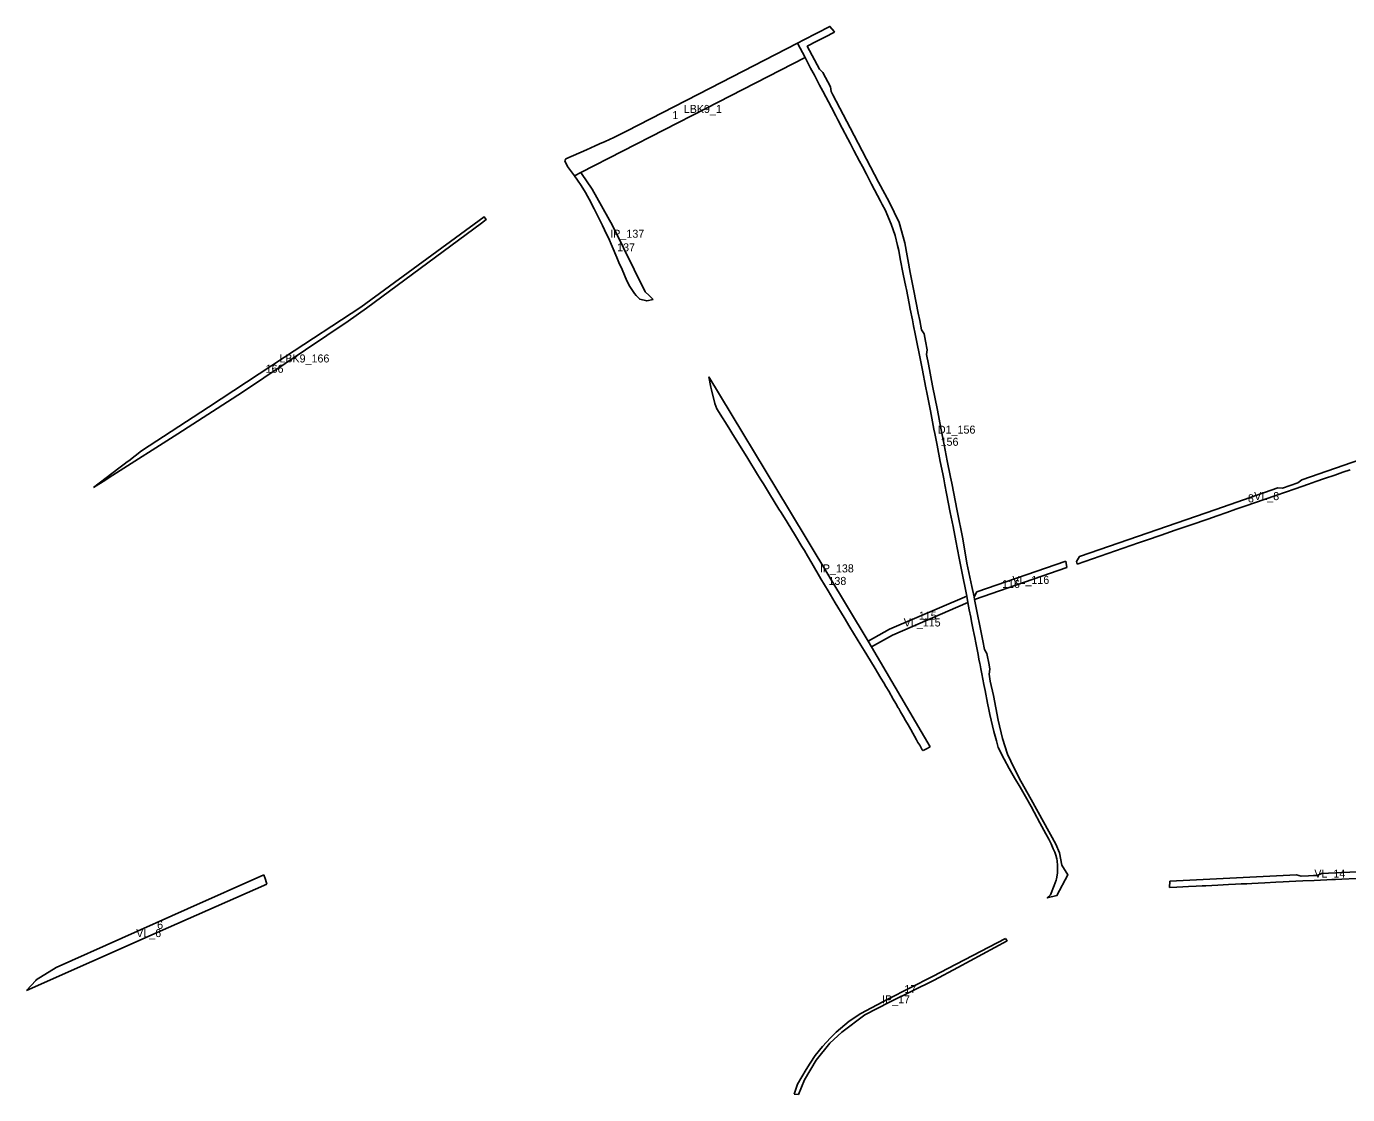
# Model space of a CAD drawing. Extents: x -521939 to -518034, y -1194984 to -1189555.
# Drawn here: x -521548 to -519897, y -1190889 to -1189555 of the extents above; entities that cross this region are included whole.
import ezdxf

# ---------------------------------------------------------------- set-up
doc = ezdxf.new("R2010")
doc.units = 0
for name, color, linetype in [('96120023', 7, 'Continuous'), ('96140023', 7, 'Continuous'), ('ID VPO', 7, 'Continuous'), ('ID VPS', 7, 'Continuous')]:
    doc.layers.add(name, color=color, linetype=linetype)

msp = doc.modelspace()

# ---------------------------------------------------------------- linework, layer by layer
at = {"layer": '96120023'}
for points in [[(-520538.07, -1189562.04), (-520538.7, -1189561.06), (-520543.9, -1189554.92), (-520576.33, -1189571.62), (-520584.33, -1189575.74), (-520574.91, -1189593.69), (-520571.87, -1189599.49), (-520567.98, -1189606.88), (-520563.29, -1189615.69), (-520556.78, -1189628.12), (-520554.77, -1189631.94), (-520552.78, -1189635.77), (-520542.06, -1189656.2), (-520536.5, -1189666.75), (-520533.97, -1189671.56), (-520528.55, -1189681.89), (-520521.58, -1189695.28), (-520518.55, -1189700.78), (-520513.98, -1189709.68), (-520506.96, -1189723.04), (-520503.29, -1189730.03), (-520498.25, -1189739.55), (-520491.89, -1189751.79), (-520480.47, -1189773.36), (-520478.5, -1189777.12), (-520474.96, -1189783.97), (-520467.22, -1189801.74), (-520462.52, -1189816.05), (-520459.4, -1189828.36), (-520457.93, -1189834.89), (-520455.88, -1189845.31), (-520452.13, -1189864.14), (-520448.96, -1189880.06), (-520448.32, -1189883.37), (-520444.85, -1189900.94), (-520443.47, -1189908.13), (-520440.81, -1189921.53), (-520439.37, -1189928.74), (-520437.33, -1189939.01), (-520429.98, -1189976.03), (-520428.73, -1189982.35), (-520424.06, -1190006.15), (-520422.85, -1190012.32), (-520421.24, -1190020.5), (-520418.36, -1190035.16), (-520413.93, -1190058), (-520412.81, -1190063.42), (-520409.99, -1190077.75), (-520405.98, -1190098.21), (-520402.94, -1190113.68), (-520401.68, -1190120.11), (-520400.22, -1190127.57), (-520398.08, -1190138.46), (-520393.44, -1190162.05), (-520389.99, -1190179.56), (-520386.49, -1190197.4), (-520382.22, -1190219.18), (-520379.42, -1190233.48), (-520372.97, -1190266.32)], [(-520371.58, -1190274.42), (-520369.76, -1190283.42), (-520368, -1190292.59), (-520366.87, -1190298.24), (-520364.88, -1190308.35), (-520363.75, -1190314.16), (-520362.96, -1190318.16), (-520361.67, -1190324.78), (-520358.8, -1190339.19), (-520357.64, -1190345.16), (-520356.65, -1190350.44), (-520356.28, -1190352.2), (-520355.24, -1190357.44), (-520354.1, -1190363.35), (-520352.77, -1190370.15), (-520351.48, -1190376.69), (-520349.98, -1190384.24), (-520346.85, -1190400.25), (-520345.34, -1190407.94), (-520344.11, -1190414.17), (-520339.16, -1190435.68), (-520335.69, -1190447.27), (-520333.6, -1190455.52), (-520326.28, -1190470.19), (-520319.79, -1190481.7), (-520313.06, -1190493.24), (-520306.18, -1190505.19), (-520299.49, -1190516.65), (-520292.56, -1190529.3), (-520288.83, -1190536.11), (-520281.56, -1190549.39), (-520273.96, -1190563.31), (-520270.32, -1190570.06), (-520267.58, -1190575.89), (-520264.82, -1190581.96), (-520262.79, -1190586.33), (-520261.69, -1190589.95), (-520260.46, -1190594.42), (-520260.08, -1190597.14), (-520259.34, -1190602.74), (-520259.34, -1190604.41), (-520259.47, -1190611.1), (-520259.64, -1190612.41), (-520260.77, -1190619.4), (-520261.32, -1190621), (-520263.6, -1190628.04), (-520268.22, -1190639.47), (-520272.31, -1190643.28), (-520260.36, -1190640.4), (-520246.6, -1190614.37), (-520254.03, -1190602.44), (-520256.94, -1190586.97), (-520261.73, -1190576.17), (-520292.37, -1190520.37), (-520305.38, -1190497.4), (-520313.7, -1190481.31), (-520322.01, -1190463.84), (-520328.19, -1190444.19), (-520333.62, -1190421.51), (-520339.48, -1190390.73), (-520343.5, -1190372.52), (-520344.85, -1190363.88), (-520343.97, -1190357.86), (-520345.06, -1190352.29), (-520347.86, -1190338.07), (-520350.9, -1190332.99), (-520352.86, -1190322.18), (-520363.12, -1190270.76), (-520363.78, -1190267.42), (-520366.37, -1190254.23), (-520372.66, -1190225.12), (-520377.99, -1190195.02), (-520384.87, -1190160.07), (-520391.56, -1190125.16), (-520393.2, -1190117.89), (-520397.27, -1190097.65), (-520401.22, -1190077.65), (-520405.21, -1190056.77), (-520409.61, -1190034.24), (-520415.58, -1190003.82), (-520420.88, -1189976.82), (-520423.3, -1189964.53), (-520422.41, -1189958.68), (-520424.49, -1189948.09), (-520426.3, -1189938.88), (-520429.34, -1189933.8), (-520431.66, -1189922.07), (-520433.46, -1189912.89), (-520438.94, -1189885.01), (-520443.42, -1189862.15), (-520450.25, -1189825.06), (-520457.28, -1189799.95), (-520463.47, -1189786.79), (-520469.68, -1189773.95), (-520483.13, -1189749.49), (-520518.67, -1189681.41), (-520540.29, -1189640.25), (-520542.46, -1189636.12), (-520543.28, -1189630.26), (-520552.66, -1189612.4), (-520557.02, -1189608.4), (-520572.14, -1189579.59), (-520568.14, -1189577.53), (-520564.14, -1189575.47), (-520555.14, -1189570.83), (-520546.14, -1189566.2), (-520542.1, -1189564.12), (-520538.07, -1189562.04)], [(-520855.05, -1189737.39), (-520862.97, -1189741.45)], [(-520854.52, -1189738.05), (-520855.05, -1189737.39)], [(-520769.62, -1189891.18), (-520774.69, -1189886.48), (-520815.47, -1189803.6), (-520840.73, -1189757.97), (-520853.99, -1189738.71), (-520854.52, -1189738.05)], [(-520862.97, -1189741.45), (-520859.09, -1189746.74)], [(-520859.09, -1189746.74), (-520854.49, -1189753.78)], [(-520854.49, -1189753.78), (-520848.98, -1189762.26)], [(-520848.98, -1189762.26), (-520842.22, -1189775.08)], [(-520842.22, -1189775.08), (-520840.25, -1189778.89)], [(-520840.25, -1189778.89), (-520838.28, -1189782.7)], [(-520838.28, -1189782.7), (-520827.89, -1189803.41)], [(-520827.89, -1189803.41), (-520822.82, -1189814.19)], [(-520822.82, -1189814.19), (-520820.55, -1189819.14)], [(-520820.55, -1189819.14), (-520815.85, -1189829.79)], [(-520815.85, -1189829.79), (-520809.87, -1189843.72)], [(-520809.87, -1189843.72), (-520807.32, -1189849.61)], [(-520807.32, -1189849.61), (-520803.4, -1189858.68)], [(-520803.4, -1189858.68), (-520797.65, -1189872.73)], [(-520797.65, -1189872.73), (-520793.8, -1189879.57)], [(-520793.8, -1189879.57), (-520788.07, -1189888.65)], [(-520788.07, -1189888.65), (-520785.91, -1189890.86)], [(-520785.91, -1189890.86), (-520781.3, -1189895.57), (-520772.63, -1189897.76), (-520764.56, -1189895.88)], [(-520764.56, -1189895.88), (-520769.62, -1189891.18)], [(-520595.57, -1190157.59), (-520694.98, -1189992.45)], [(-520694.98, -1189992.45), (-520692.55, -1190005.5)], [(-520692.55, -1190005.5), (-520691.84, -1190008.79)], [(-520691.84, -1190008.79), (-520687.51, -1190025.96)], [(-520687.51, -1190025.96), (-520685.06, -1190032.49)], [(-520685.06, -1190032.49), (-520678.04, -1190043.73)], [(-520678.04, -1190043.73), (-520674.3, -1190049.78)], [(-520674.3, -1190049.78), (-520668.96, -1190058.36)], [(-519742.92, -1190048.01), (-519787.45, -1190063.39), (-519954.51, -1190121.09), (-519959.21, -1190124.83), (-519978.27, -1190131.41), (-519984.27, -1190131.37), (-520061.95, -1190158.2), (-520231.96, -1190216.92), (-520235.61, -1190223.15)], [(-520668.96, -1190058.36), (-520664.99, -1190064.75), (-520649.81, -1190089.25)], [(-520649.81, -1190089.25), (-520646.54, -1190094.49)], [(-520646.54, -1190094.49), (-520634.26, -1190114.38)], [(-520634.26, -1190114.38), (-520630.08, -1190121.08)], [(-519936.96, -1190123.44), (-519926.15, -1190119.68)], [(-519926.15, -1190119.68), (-519913.25, -1190115.28)], [(-519913.25, -1190115.28), (-519903.02, -1190111.63)], [(-519903.02, -1190111.63), (-519893.94, -1190108.6)], [(-520630.08, -1190121.08), (-520626.81, -1190126.38)], [(-520626.81, -1190126.38), (-520619.25, -1190138.59)], [(-519986.68, -1190140.64), (-519962.62, -1190132.36)], [(-519962.62, -1190132.36), (-519946.2, -1190126.69)], [(-519946.2, -1190126.69), (-519936.96, -1190123.44)], [(-520619.25, -1190138.59), (-520607.45, -1190157.65)], [(-520024.36, -1190153.64), (-520013.6, -1190149.97)], [(-520013.6, -1190149.97), (-519986.68, -1190140.64)], [(-520607.45, -1190157.65), (-520604.7, -1190162.17)], [(-520604.7, -1190162.17), (-520597.31, -1190174.18)], [(-520496.15, -1190322.74), (-520595.57, -1190157.59)], [(-520071.81, -1190170.12), (-520060.18, -1190166.05), (-520048.21, -1190161.91)], [(-520048.21, -1190161.91), (-520036.77, -1190157.93)], [(-520036.77, -1190157.93), (-520024.36, -1190153.64)], [(-520597.31, -1190174.18), (-520586.78, -1190191.32)], [(-520129.95, -1190190.13), (-520112.49, -1190184.08)], [(-520112.49, -1190184.08), (-520092.49, -1190177.21)], [(-520092.49, -1190177.21), (-520071.81, -1190170.12)], [(-520586.78, -1190191.32), (-520578.85, -1190204.26)], [(-520235.01, -1190226.44), (-520158.52, -1190200.01)], [(-520158.52, -1190200.01), (-520148.48, -1190196.56)], [(-520148.48, -1190196.56), (-520129.95, -1190190.13)], [(-520578.85, -1190204.26), (-520575.54, -1190209.65)], [(-520575.54, -1190209.65), (-520571.92, -1190216.03)], [(-520571.92, -1190216.03), (-520566.46, -1190225.16)], [(-520566.46, -1190225.16), (-520555.01, -1190244.86)], [(-520249.16, -1190222.86), (-520360.13, -1190261.18), (-520363.78, -1190267.42)], [(-520363.12, -1190270.76), (-520247.81, -1190230.86)], [(-520247.81, -1190230.86), (-520249.16, -1190222.86)], [(-520235.61, -1190223.15), (-520235.01, -1190226.44)], [(-520555.01, -1190244.86), (-520546, -1190259.94)], [(-520546, -1190259.94), (-520537.12, -1190274.8)], [(-520372.97, -1190266.32), (-520469.39, -1190307.83)], [(-520371.58, -1190274.42), (-520372.97, -1190266.32)], [(-520372.97, -1190266.32), (-520371.58, -1190274.42)], [(-520363.78, -1190267.42), (-520363.12, -1190270.76)], [(-520537.12, -1190274.8), (-520525.87, -1190293.08)], [(-520465.85, -1190315.02), (-520371.58, -1190274.42)], [(-520525.87, -1190293.08), (-520518.77, -1190305.18)], [(-520518.77, -1190305.18), (-520505.06, -1190327.7)], [(-520469.39, -1190307.83), (-520496.15, -1190322.74)], [(-520492.06, -1190329.61), (-520465.85, -1190315.02)], [(-520505.06, -1190327.7), (-520500.89, -1190334.53)], [(-520500.89, -1190334.53), (-520493.14, -1190347.28)], [(-520492.06, -1190329.61), (-520496.15, -1190322.74)], [(-520496.15, -1190322.74), (-520492.06, -1190329.61)], [(-520418.63, -1190454.51), (-520492.06, -1190329.61)], [(-520493.14, -1190347.28), (-520487.23, -1190356.63)], [(-520487.23, -1190356.63), (-520484.26, -1190361.73)], [(-520484.26, -1190361.73), (-520480.03, -1190368.97)], [(-520480.03, -1190368.97), (-520476.65, -1190374.74)], [(-520476.65, -1190374.74), (-520474.06, -1190379.19)], [(-520474.06, -1190379.19), (-520470.42, -1190385.29)], [(-520470.42, -1190385.29), (-520464.79, -1190395.13)], [(-520464.79, -1190395.13), (-520461.6, -1190400.68)], [(-520461.6, -1190400.68), (-520458.54, -1190405.84)], [(-520458.54, -1190405.84), (-520457.88, -1190406.97)], [(-520457.88, -1190406.97), (-520455.54, -1190411.02)], [(-520455.54, -1190411.02), (-520452.05, -1190417.09)], [(-520452.05, -1190417.09), (-520449.33, -1190421.77)], [(-520449.33, -1190421.77), (-520446.15, -1190427.25)], [(-520446.15, -1190427.25), (-520442.94, -1190432.82)], [(-520442.94, -1190432.82), (-520435.78, -1190445.73)], [(-520435.78, -1190445.73), (-520433.93, -1190449.11), (-520431.58, -1190452.47)], [(-520431.58, -1190452.47), (-520428.66, -1190458.29), (-520427.37, -1190459.39)], [(-520427.37, -1190459.39), (-520423.37, -1190457.05)], [(-520423.37, -1190457.05), (-520418.63, -1190454.51)], [(-521251.04, -1190614.64), (-521346.43, -1190657.14), (-521510.56, -1190730.26)], [(-521249.05, -1190620.36), (-521251.04, -1190614.64)], [(-519955.34, -1190616.3), (-519961.08, -1190614.58), (-520119.28, -1190622.29)], [(-519939.78, -1190615.54), (-519946.03, -1190615.85)], [(-519693.24, -1190601.52), (-519752.34, -1190604.4), (-519929.64, -1190613.04), (-519935.19, -1190615.32), (-519939.78, -1190615.54)], [(-521384.14, -1190686.63), (-521247.06, -1190626.08)], [(-521247.06, -1190626.08), (-521249.05, -1190620.36)], [(-520119.28, -1190622.29), (-520119.46, -1190630.32)], [(-520119.46, -1190630.32), (-520110.38, -1190629.91)], [(-520110.38, -1190629.91), (-520102.91, -1190629.55)], [(-520102.91, -1190629.55), (-520095.81, -1190629.12)], [(-520095.81, -1190629.12), (-520086.43, -1190628.7)], [(-520086.43, -1190628.7), (-520078.68, -1190628.32)], [(-520078.68, -1190628.32), (-520074.1, -1190628.1)], [(-520074.1, -1190628.1), (-520059.37, -1190627.38)], [(-520059.37, -1190627.38), (-520045.77, -1190626.72)], [(-520045.77, -1190626.72), (-520037.2, -1190626.26)], [(-520037.2, -1190626.26), (-520030.12, -1190625.96)], [(-520030.12, -1190625.96), (-520023.13, -1190625.6)], [(-520023.13, -1190625.6), (-520016.69, -1190625.32)], [(-520016.69, -1190625.32), (-520008.95, -1190624.91)], [(-520008.95, -1190624.91), (-520000.46, -1190624.51)], [(-520000.46, -1190624.51), (-519986.76, -1190623.81)], [(-519986.76, -1190623.81), (-519977.56, -1190623.39)], [(-519977.56, -1190623.39), (-519970.21, -1190623.03)], [(-519970.21, -1190623.03), (-519961.73, -1190622.55)], [(-519961.73, -1190622.55), (-519953.25, -1190622.2)], [(-519946.03, -1190615.85), (-519955.34, -1190616.3)], [(-519953.25, -1190622.2), (-519938.98, -1190621.52)], [(-519938.98, -1190621.52), (-519923.22, -1190620.76)], [(-519923.22, -1190620.76), (-519916.75, -1190620.41)], [(-519916.75, -1190620.41), (-519912.12, -1190620.15)], [(-519912.12, -1190620.15), (-519904.19, -1190619.79)], [(-519904.19, -1190619.79), (-519886.32, -1190618.93)], [(-521547.56, -1190758.81), (-521384.14, -1190686.63)], [(-520579.33, -1190879.67), (-520575.39, -1190870.36), (-520560.86, -1190845.88), (-520544.03, -1190824.72), (-520528.99, -1190810.95), (-520500.11, -1190789.41), (-520469.27, -1190773.73), (-520413.62, -1190746.07), (-520383.85, -1190730.39), (-520322.54, -1190696.8), (-520323.5, -1190695.35)], [(-520324.46, -1190693.89), (-520386.14, -1190726.13)], [(-520323.5, -1190695.35), (-520324.46, -1190693.89)], [(-521510.56, -1190730.26), (-521535.38, -1190745.68)], [(-520386.14, -1190726.13), (-520415.61, -1190741.57)], [(-521535.38, -1190745.68), (-521536.01, -1190746.36), (-521547.56, -1190758.81)], [(-520415.61, -1190741.57), (-520471.38, -1190769.62), (-520505.39, -1190787.53)], [(-520505.39, -1190787.53), (-520519.61, -1190797.43), (-520536.03, -1190811)], [(-520536.03, -1190811), (-520543.12, -1190818.16)], [(-520553.22, -1190828.97), (-520562.17, -1190840.06)], [(-520543.12, -1190818.16), (-520553.22, -1190828.97)], [(-520562.17, -1190840.06), (-520568.69, -1190849.57), (-520573.57, -1190857.84)], [(-520573.57, -1190857.84), (-520584.48, -1190876.05)], [(-520584.48, -1190876.05), (-520588.66, -1190888.36)], [(-520588.66, -1190888.36), (-520583.27, -1190888.97)], [(-520583.27, -1190888.97), (-520579.33, -1190879.67)]]:
    msp.add_lwpolyline(points, dxfattribs=at)
at = {"layer": '96140023'}
for points in [[(-520584.33, -1189575.74), (-520693.52, -1189631.98), (-520798.15, -1189685.87)], [(-520574.91, -1189593.69), (-520584.33, -1189575.74)], [(-520855.05, -1189737.39), (-520698.86, -1189657.27), (-520574.91, -1189593.69)], [(-520798.15, -1189685.87), (-520813.62, -1189693.84)], [(-520836.95, -1189704.12), (-520848.1, -1189709.03)], [(-520832.44, -1189702.13), (-520836.95, -1189704.12)], [(-520831.59, -1189701.76), (-520832.44, -1189702.13)], [(-520824.7, -1189698.73), (-520831.59, -1189701.76)], [(-520813.62, -1189693.84), (-520824.7, -1189698.73)], [(-520873.85, -1189720.38), (-520875.18, -1189722.65)], [(-520875.18, -1189722.65), (-520871.46, -1189729.85)], [(-520848.1, -1189709.03), (-520873.85, -1189720.38)], [(-520871.46, -1189729.85), (-520862.97, -1189741.45)], [(-520862.97, -1189741.45), (-520855.05, -1189737.39)], [(-520979.19, -1189800.51), (-520973.26, -1189796.11), (-520974.53, -1189794.42), (-520975.8, -1189792.72), (-521129.95, -1189905.7), (-521225, -1189967.98), (-521320.06, -1190030.25), (-521403.82, -1190085.13), (-521419.72, -1190097.27), (-521421.67, -1190098.76), (-521425.29, -1190101.52), (-521432.08, -1190106.71), (-521463.67, -1190130.83)], [(-521122.58, -1189906.88), (-520979.19, -1189800.51)], [(-521277.58, -1190011.81), (-521145.53, -1189923.09), (-521122.58, -1189906.88)], [(-521358.54, -1190063.68), (-521277.58, -1190011.81)], [(-521439.5, -1190115.54), (-521358.54, -1190063.68)], [(-521451.59, -1190123.19), (-521439.5, -1190115.54)], [(-521463.67, -1190130.83), (-521451.59, -1190123.19)]]:
    msp.add_lwpolyline(points, dxfattribs=at)

# ---------------------------------------------------------------- texts
at = {"layer": '96120023'}
for s, rotation, p in [('IP_137', 0, (-520818.17, -1189818.82)), ('D1_156', 360, (-520408.96, -1190063.48)), ('VL_8', 0, (-520013.87, -1190146.53)), ('IP_138', 360, (-520556.39, -1190236.81)), ('VL_116', 0, (-520315.95, -1190251.16)), ('VL_115', 360, (-520451.64, -1190304.32)), ('VL_14', 0, (-519938.7, -1190618.02)), ('VL_6', 0, (-521410.41, -1190692.29)), ('IP_17', 0, (-520478.75, -1190775.06))]:
    msp.add_text(s, height=10, rotation=rotation, dxfattribs=at).set_placement(p)
at = {"layer": '96140023'}
for s, p in [('LBK9_1', (-520726.43, -1189662.96)), ('LBK9_166', (-521231.58, -1189974.6))]:
    msp.add_text(s, height=10, rotation=0, dxfattribs=at).set_placement(p)
at = {"layer": 'ID VPO'}
for s, rotation, p in [('1', 360, (-520740.65, -1189670.65)), ('166', 0, (-521248.75, -1189987.46))]:
    msp.add_text(s, height=10, rotation=rotation, dxfattribs=at).set_placement(p)
at = {"layer": 'ID VPS'}
for s, rotation, p in [('137', 360, (-520809.66, -1189835.83)), ('156', 360, (-520405.59, -1190078.67)), ('8', 360, (-520021.6, -1190149.21)), ('138', 360, (-520545.68, -1190252.43)), ('116', 0, (-520328.83, -1190256.27)), ('115', 0, (-520432.76, -1190295.8)), ('6', 360, (-521384.26, -1190682.06)), ('17', 360, (-520450.82, -1190762.14))]:
    msp.add_text(s, height=10, rotation=rotation, dxfattribs=at).set_placement(p)

doc.saveas('drawing.dxf')
